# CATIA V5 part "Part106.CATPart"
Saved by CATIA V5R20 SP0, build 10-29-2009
Part number: 9FA 063212
Revision: ANY
Definition: UNKNOWN
Nomenclature: 9FA 063212
Source: Unknown
Bounding box of the stored display mesh (mm): x -3 to 3, y -9.95 to 10.05, z -3 to 3
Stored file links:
  C:\Users\Utente\Desktop\IO LAVORO\3D X SITO CF\CUMSA\3D files FA\FA 063212-20\Part106.CATPart

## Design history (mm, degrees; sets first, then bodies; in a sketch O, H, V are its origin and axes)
Body1 "Cortar-Extruir5" (main body)
  Solid1: solid without history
